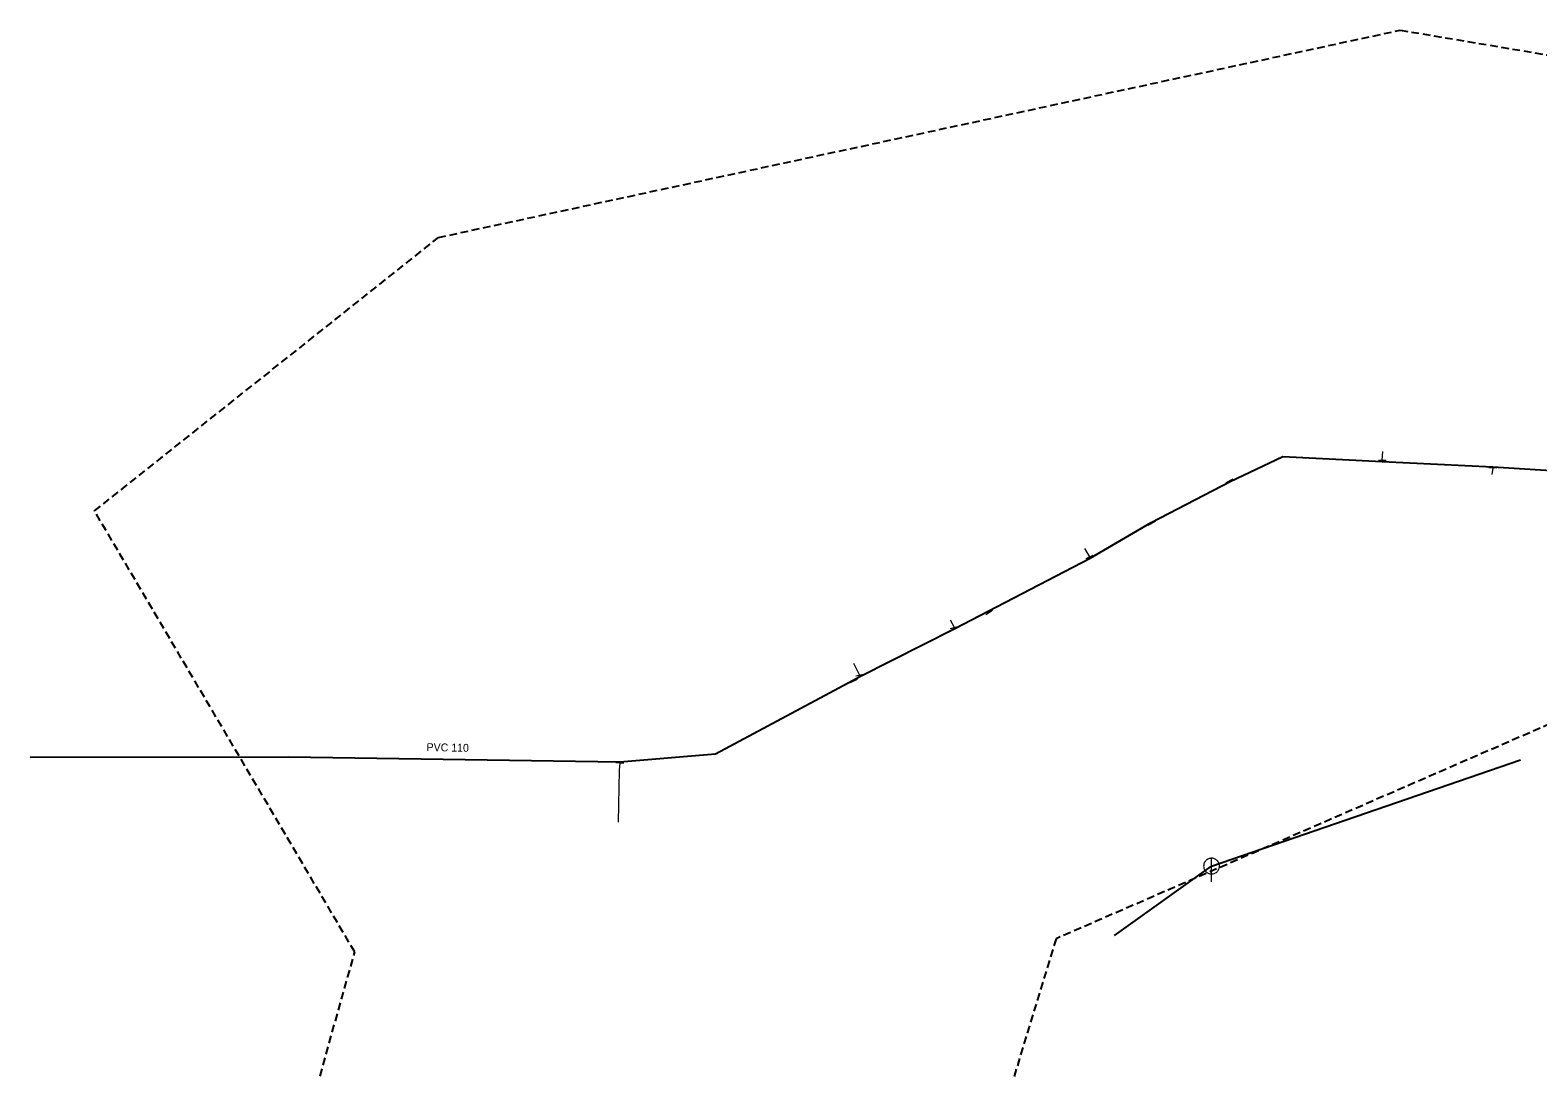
# Model space of a CAD drawing. Extents: x -693324 to -693034, y -967499 to -967236.
# Drawn here: x -693323.5 to -693132.7, y -967367.9 to -967236.5 of the extents above; entities that cross this region are included whole.
import ezdxf

# ---------------------------------------------------------------- set-up
doc = ezdxf.new("R2010")
doc.units = 0
doc.header["$LTSCALE"] = 0.32
doc.linetypes.add('MEDIUM_DASHED', pattern=[4.5, 3, -1.5])
doc.layers.add('1', color=7, linetype='Continuous')
for name, color, linetype, lineweight in [('13', 7, 'Continuous', 13), ('14', 7, 'Continuous', 13), ('17', 7, 'Continuous', 25), ('22', 7, 'Continuous', 13), ('34', 7, 'Continuous', 13), ('63', 7, 'MEDIUM_DASHED', 25)]:
    doc.layers.add(name, color=color, linetype=linetype, lineweight=lineweight)

msp = doc.modelspace()

# ---------------------------------------------------------------- linework, layer by layer
at = {"layer": '13'}
for p, q in [((-693152.399, -967290.879), (-693152.35, -967289.77)), ((-693138.41, -967291.87), (-693138.52, -967292.68)), ((-693189.42, -967303.12), (-693190.03, -967302.05)), ((-693206.55, -967312.059), (-693207.059, -967311.12)), ((-693218.55, -967318.059), (-693219.27, -967316.609))]:
    msp.add_line(p, q, dxfattribs=at)
msp.add_lwpolyline([(-693248.89, -967329.219), (-693248.949, -967330.1), (-693249.117, -967336.697)], dxfattribs=at)
at = {"layer": '14'}
for p, q in [((-693152.395, -967291.03), (-693152.399, -967290.879)), ((-693138.401, -967291.732), (-693138.41, -967291.87)), ((-693171.636, -967293.58), (-693171.699, -967293.46)), ((-693181.64, -967298.771), (-693181.57, -967298.899)), ((-693189.353, -967303.264), (-693189.42, -967303.12)), ((-693202.254, -967310.005), (-693202.149, -967310.18)), ((-693206.508, -967312.196), (-693206.55, -967312.059)), ((-693219.356, -967318.705), (-693219.28, -967318.859)), ((-693218.51, -967318.239), (-693218.55, -967318.059)), ((-693248.902, -967329.07), (-693248.89, -967329.219))]:
    msp.add_line(p, q, dxfattribs=at)
at = {"layer": '14', "lineweight": 25}
msp.add_lwpolyline([(-693186.272, -967351.034), (-693174.006, -967342.261), (-693134.916, -967328.811)], dxfattribs=at)
at = {"layer": '17'}
msp.add_lwpolyline([(-693323.507, -967328.463), (-693290.828, -967328.409), (-693248.902, -967329.07), (-693236.776, -967328.039), (-693219.356, -967318.705), (-693218.51, -967318.239), (-693206.508, -967312.196), (-693202.254, -967310.005), (-693189.353, -967303.264), (-693181.64, -967298.771), (-693171.636, -967293.58), (-693165, -967290.405), (-693152.395, -967291.03), (-693138.401, -967291.732), (-693128.998, -967292.313), (-693123.179, -967292.464), (-693111.031, -967292.944), (-693098.903, -967293.209), (-693096.13, -967293.27), (-693094.567, -967293.283)], dxfattribs=at)
at = {"layer": '22'}
msp.add_line((-693174.006, -967344.261), (-693174.005, -967341.261), dxfattribs=at)
msp.add_lwpolyline([(-693173.006, -967342.261), (-693173.011, -967342.152), (-693173.029, -967342.044), (-693173.059, -967341.938), (-693173.099, -967341.837), (-693173.151, -967341.74), (-693173.213, -967341.65), (-693173.285, -967341.567), (-693173.365, -967341.493), (-693173.453, -967341.427), (-693173.547, -967341.372), (-693173.647, -967341.327), (-693173.752, -967341.294), (-693173.859, -967341.272), (-693173.968, -967341.262), (-693174.078, -967341.264), (-693174.186, -967341.278), (-693174.293, -967341.303), (-693174.396, -967341.34), (-693174.494, -967341.389), (-693174.586, -967341.447), (-693174.672, -967341.516), (-693174.749, -967341.593), (-693174.818, -967341.679), (-693174.877, -967341.771), (-693174.925, -967341.869), (-693174.962, -967341.972), (-693174.988, -967342.079), (-693175.002, -967342.187), (-693175.005, -967342.297), (-693174.995, -967342.406), (-693174.974, -967342.513), (-693174.94, -967342.617), (-693174.896, -967342.717), (-693174.841, -967342.812), (-693174.775, -967342.9), (-693174.701, -967342.98), (-693174.618, -967343.052), (-693174.528, -967343.114), (-693174.432, -967343.166), (-693174.33, -967343.207), (-693174.225, -967343.237), (-693174.117, -967343.255), (-693174.007, -967343.261), (-693173.898, -967343.255), (-693173.79, -967343.237), (-693173.685, -967343.208), (-693173.583, -967343.167), (-693173.486, -967343.115), (-693173.396, -967343.053), (-693173.313, -967342.982), (-693173.238, -967342.902), (-693173.173, -967342.814), (-693173.117, -967342.72), (-693173.073, -967342.62), (-693173.039, -967342.516), (-693173.017, -967342.408), (-693173.007, -967342.299)], close=True, dxfattribs=at)
at = {"layer": '34'}
for p, q in [((-693152.898, -967290.893), (-693151.899, -967290.865)), ((-693137.91, -967291.9), (-693138.908, -967291.838)), ((-693172.141, -967293.693), (-693171.256, -967293.227)), ((-693181.131, -967298.658), (-693182.008, -967299.139)), ((-693189.873, -967303.331), (-693188.966, -967302.909)), ((-693201.72, -967309.922), (-693202.578, -967310.436)), ((-693207.028, -967312.204), (-693206.071, -967311.914)), ((-693218.832, -967318.636), (-693219.728, -967319.081)), ((-693219.038, -967318.167), (-693218.061, -967317.951)), ((-693248.391, -967329.252), (-693249.388, -967329.184))]:
    msp.add_line(p, q, dxfattribs=at)
at = {"layer": '63'}
msp.add_lwpolyline([(-693215.442, -967470.355), (-693268.475, -967499.384), (-693268.475, -967499.384), (-693301.969, -967422.904), (-693301.969, -967422.904), (-693282.431, -967353.124), (-693282.431, -967353.124), (-693315.367, -967297.3), (-693315.367, -967297.3), (-693271.824, -967262.689), (-693271.824, -967262.689), (-693150.127, -967236.451), (-693150.127, -967236.451), (-693034.013, -967255.99), (-693034.013, -967255.99), (-693048.527, -967323.537), (-693048.527, -967323.537), (-693120.541, -967319.63), (-693120.541, -967319.63), (-693193.67, -967351.449), (-693193.67, -967351.449), (-693214.325, -967418.997), (-693214.325, -967418.997)], close=True, dxfattribs=at)

# ---------------------------------------------------------------- texts
at = {"layer": '1'}
msp.add_text('PVC 110 ', height=1, rotation=359, dxfattribs=at).set_placement((-693273.349, -967327.698))

doc.saveas('drawing.dxf')
